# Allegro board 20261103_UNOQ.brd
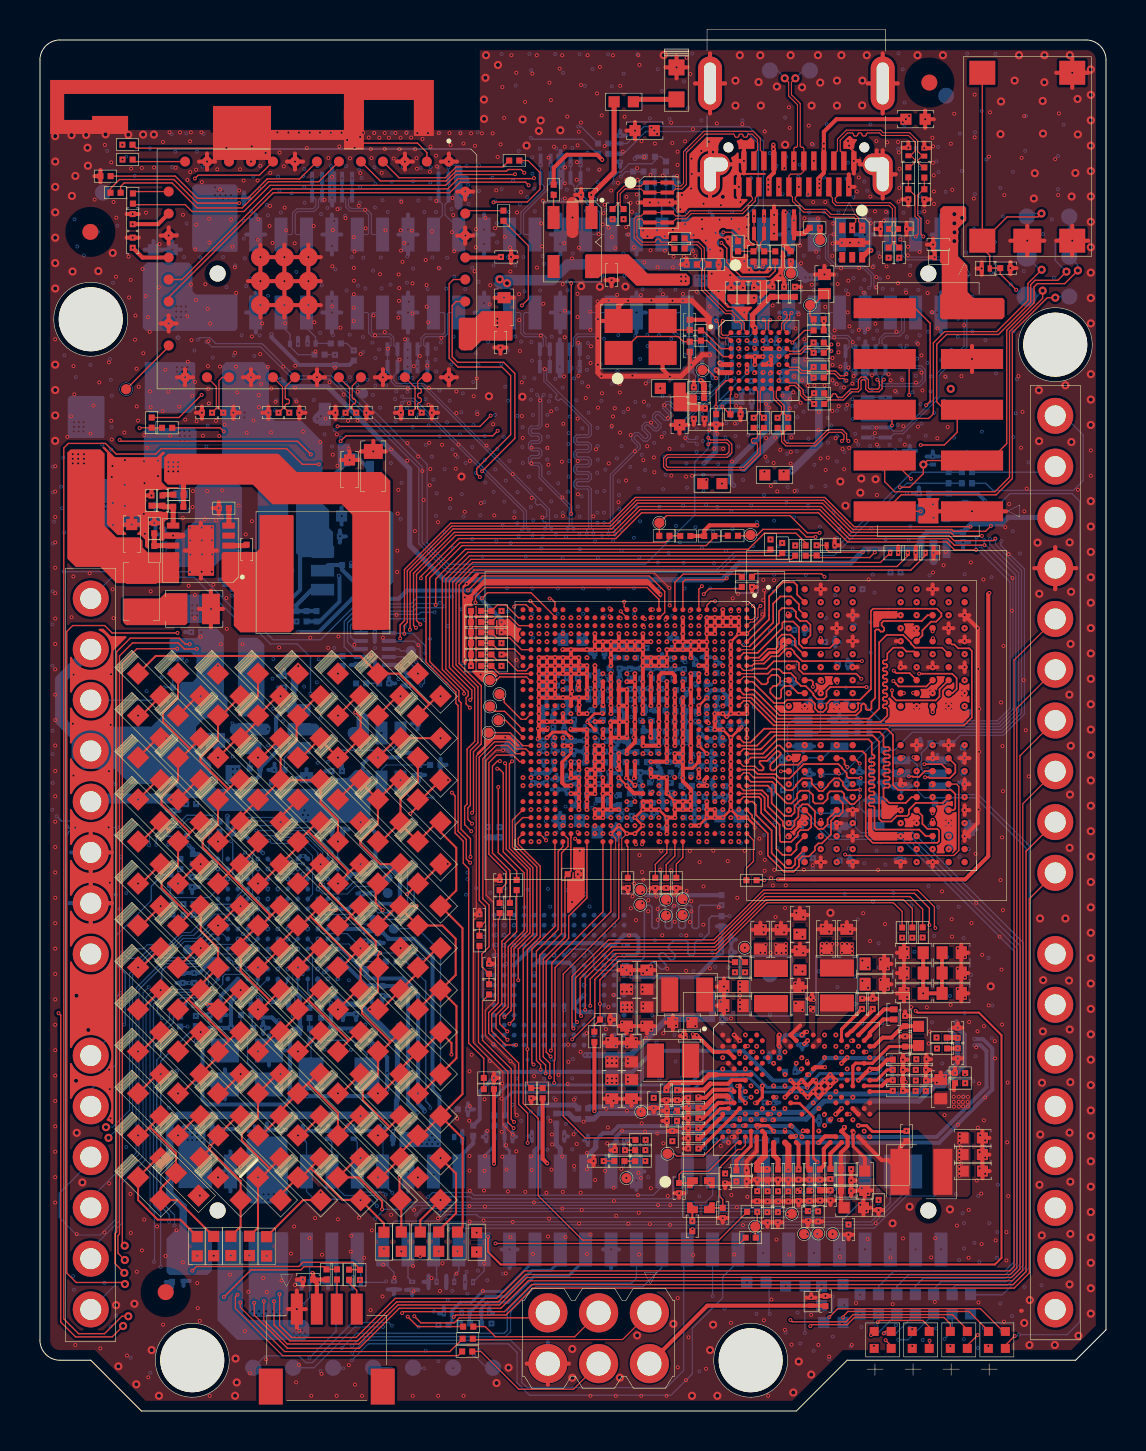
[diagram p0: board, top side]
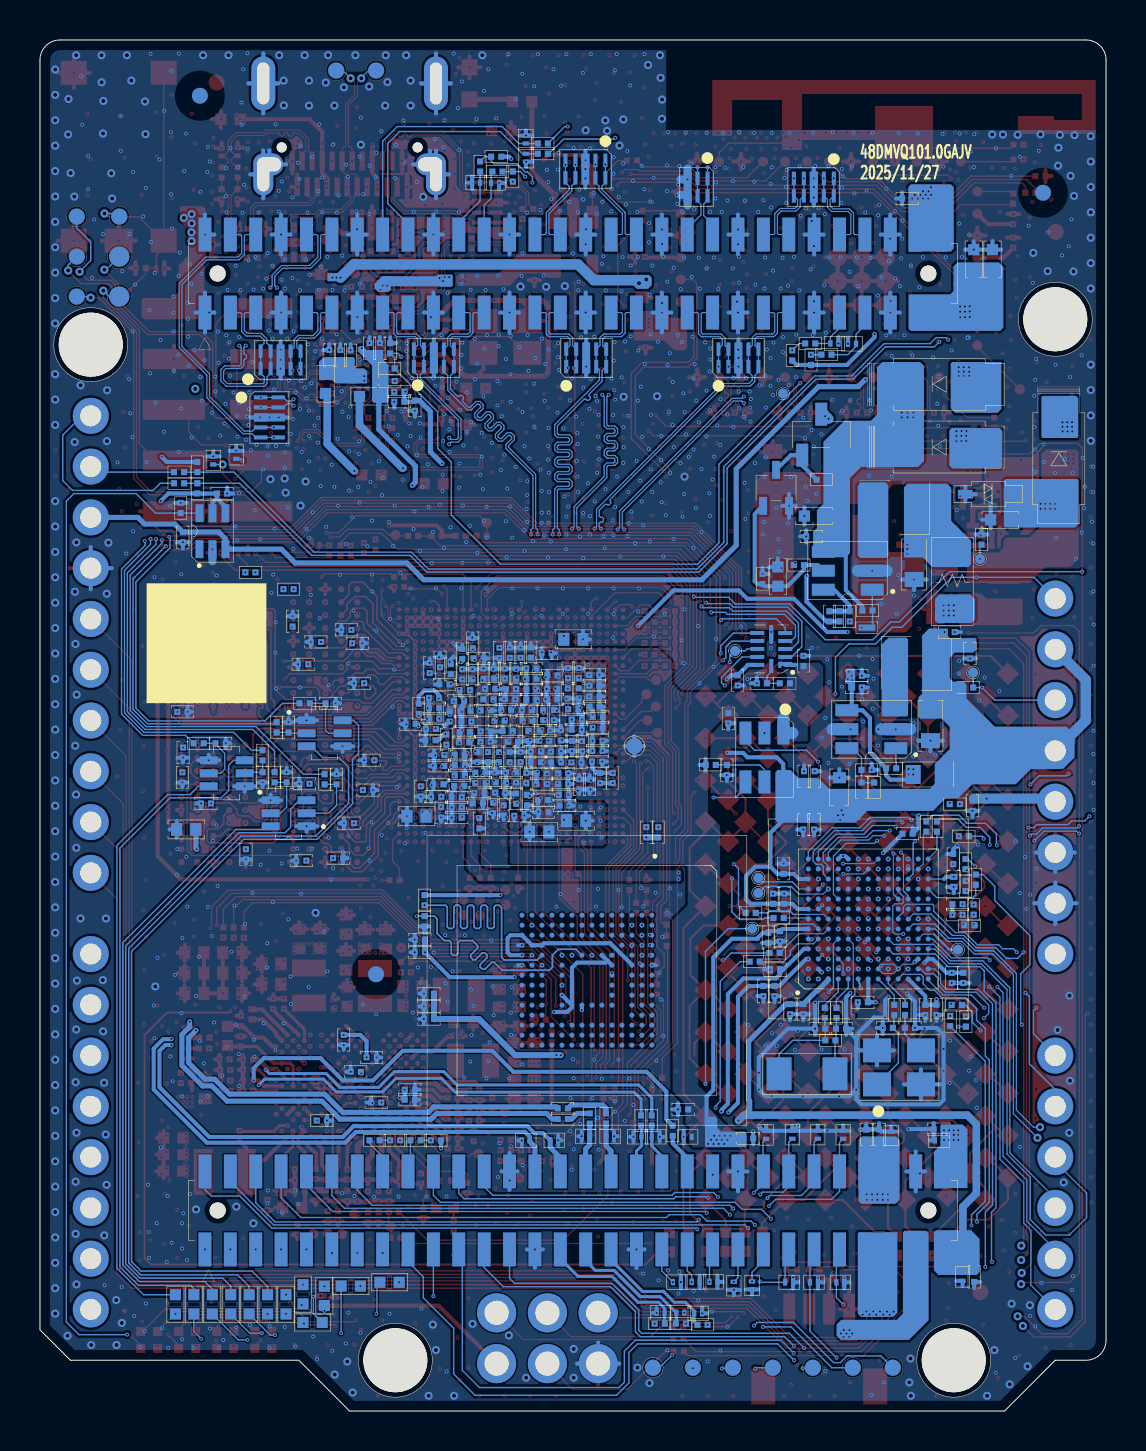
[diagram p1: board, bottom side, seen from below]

Outline 53.34 x 68.58 mm; copper layers: TOP, G2, S3, V4, V5, S6, G7, BOTTOM. Coordinates in mm from the lower left corner of the outline.
Outline path: 0,67.58 0,3.54 arc(0.29,2.83) 1,2.54 2.54,2.54 5.08,0 37.85,0 40.39,2.54 51.82,2.54 53.34,4.06 53.34,67.58 arc(53.05,68.29) 52.34,68.58 1,68.58 arc(0.29,68.29) 0,67.58

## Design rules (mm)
constraint set DEFAULT: min track width 0.066
net group DP_MUX_SSRXN1_C: nets MUX_SSRXN1_C MUX_SSRXP1_C
net group DP_MUX_SSRXN2_C: nets MUX_SSRXN2_C MUX_SSRXP2_C
net group EAR_M_R: nets EAR_M_R EAR_P_R
net group EBI0_CKE: nets EBI0_CKE_0 EBI0_CKE_1
net group EBI0_CLK: nets EBI0_CLK_M EBI0_CLK_P
net group EBI0_DQS_0: nets EBI0_DQS_0_M EBI0_DQS_0_P
net group EBI0_DQS_1: nets EBI0_DQS_1_M EBI0_DQS_1_P
net group EBI1_CKE: nets EBI1_CKE_0 EBI1_CKE_1
net group EBI1_CLK: nets EBI1_CLK_M EBI1_CLK_P
net group EBI1_DQS_0: nets EBI1_DQS_0_M EBI1_DQS_0_P
net group EBI1_DQS_1: nets EBI1_DQS_1_M EBI1_DQS_1_P
net group LINEOUT: nets LINEOUT_M LINEOUT_P
net group LINEOUT_CONN: nets LINEOUT_M_CONN LINEOUT_P_CONN
net group LINEOUT_P_C: nets LINEOUT_M_C LINEOUT_P_C
net group MG_CMD: nets WL_CMD_CLK WL_CMD_DATA
net group MIPI_DSI0_CLK_M: nets MIPI_DSI0_CLK_M MIPI_DSI0_CLK_M_CONN
net group MIPI_DSI0_CLK_P: nets MIPI_DSI0_CLK_P MIPI_DSI0_CLK_P_CONN
net group MIPI_DSI0_L0_M: nets MIPI_DSI0_L0_M MIPI_DSI0_L0_M_CONN
net group MIPI_DSI0_L0_P: nets MIPI_DSI0_L0_P MIPI_DSI0_L0_P_CONN
net group MIPI_DSI0_L1_M: nets MIPI_DSI0_L1_M MIPI_DSI0_L1_M_CONN
net group MIPI_DSI0_L1_P: nets MIPI_DSI0_L1_P MIPI_DSI0_L1_P_CONN
net group MIPI_DSI0_L3_M: nets MIPI_DSI0_L3_M MIPI_DSI0_L3_M_CONN
net group MIPI_DSI0_L3_P: nets MIPI_DSI0_L3_P MIPI_DSI0_L3_P_CONN
net group MUX_SBU1: nets MUX_SBU1 SBU1_AUXP
net group MUX_SBU2: nets MUX_SBU2 SBU2_AUXN
net group MUX_SSRXN2: nets MUX_SSRXN2 MUX_SSRXP2
net group MUX_SSRXP1: nets MUX_SSRXN1 MUX_SSRXP1
net group MUX_SSTXN1_C: nets MUX_SSTXN1 MUX_SSTXP1
net group MUX_SSTXN2: nets MUX_SSTXN2 MUX_SSTXP2
net group MUX_SSTXN2_C: nets MUX_SSTXN2_C MUX_SSTXP2_C
net group MUX_SSTXP1_C: nets MUX_SSTXN1_C MUX_SSTXP1_C
net group SDC1_CLK: nets SDC1_CLK SDC1_CLK_TR
net group VFB_S3: nets VFB_NEG_S3 VFB_S3
net group VFB_S4: nets VFB_NEG_S4 VFB_S4
net group VSNS_S1A_APC: nets VSNS_S1A_APC_M VSNS_S1A_APC_P
net group VSNS_S2A_CX: nets VSNS_S2A_CX_M VSNS_S2A_CX_P
net group CLS_CRITICAL: nets SOC_I2S_D0_R SOC_I2S_SCK SOC_I2S_SCK_R SOC_I2S_WS SOC_I2S_WS_R SOC_UART_RX_SE4 SOC_UART_TX_SE4
net group CLS_LED_MATRIX: nets LED_MATRIX_0 LED_MATRIX_0_R LED_MATRIX_1 LED_MATRIX_1_R LED_MATRIX_2 LED_MATRIX_2_R LED_MATRIX_3 LED_MATRIX_3_R LED_MATRIX_4 LED_MATRIX_4_R LED_MATRIX_5 LED_MATRIX_5_R LED_MATRIX_6 LED_MATRIX_6_R LED_MATRIX_7 LED_MATRIX_7_R LED_MATRIX_8 LED_MATRIX_8_R LED_MATRIX_9 LED_MATRIX_9_R LED_MATRIX_10 LED_MATRIX_10_R LED_MATRIX_11
net group CLS_POWER: nets AVDD1P0V AVDD1P8V AVDD3P0V DVDD1P0V DVDD1P8V VBUS_DIV8 VCOIN VCONN_IN VREF_LPDDR3 VREF_MSM_1P25V VREF_TXDAC_1P25V VREG_L3A_0P6V VREG_L4A_2P96V VREG_L5A_1P232V VREG_L6A_0P9V VREG_L7A_0P664V VREG_L8A_1P0V VREG_L9A_1P0V VREG_L10A_1P3V VREG_L11A_1P0V VREG_L12A_0P9V VREG_L13A_1P8V VREG_L14A_1P8V VREG_L16A_1P8V VREG_L17A_3P0V VREG_L18A_1P8V VREG_L19A_1P8V VREG_L21A_2P96V VREG_L22A_3P3V VREG_S1A_0P8V VREG_XO VSW_S1 VSW_S2 VSW_S3 VSW_S4
net group CLS_SINGEL-50R: nets ANT_CH0 FM_ANT LNBBCLK1 LNBBCLK2 LNBBCLK2_R MUX_XTAL_IN MUX_XTAL_OUT RFCLK2 RTC_SLEEP_CLK RTC_SLEEP_CLK_R SLEEP_CLK SM_LNBBCLK1 SWR_RX_CLK SWR_RX_CLK_R SWR_RX_DATA0 SWR_RX_DATA0_R SWR_RX_DATA1 SWR_RX_DATA1_R SWR_TX_CLK SWR_TX_CLK_R SWR_TX_DATA0 SWR_TX_DATA0_R WCN_RFCLK2 WCN_RFCLK2_R WLAN_XO_CLK
net group EBI0_CA_CS: nets EBI0_CA_0 EBI0_CA_1 EBI0_CA_2 EBI0_CA_3 EBI0_CA_4 EBI0_CA_5 EBI0_CS_0 EBI0_CS_1
net group EBI0_DQ0-7: nets EBI0_DMI_0 EBI0_DQ0 EBI0_DQ1 EBI0_DQ2 EBI0_DQ3 EBI0_DQ4 EBI0_DQ5 EBI0_DQ6 EBI0_DQ7
net group EBI0_DQ8_15: nets EBI0_DMI_1 EBI0_DQ8 EBI0_DQ9 EBI0_DQ10 EBI0_DQ11 EBI0_DQ12 EBI0_DQ13 EBI0_DQ14 EBI0_DQ15
net group EBI1_CA_CS: nets EBI1_CA_0 EBI1_CA_1 EBI1_CA_2 EBI1_CA_3 EBI1_CA_4 EBI1_CA_5 EBI1_CS_0 EBI1_CS_1
net group EBI1_DQ0_7: nets EBI1_DMI_0 EBI1_DQ0 EBI1_DQ1 EBI1_DQ2 EBI1_DQ3 EBI1_DQ4 EBI1_DQ5 EBI1_DQ6 EBI1_DQ7
net group EBI1_DQ8_15: nets EBI1_DMI_1 EBI1_DQ8 EBI1_DQ9 EBI1_DQ10 EBI1_DQ11 EBI1_DQ12 EBI1_DQ13 EBI1_DQ14 EBI1_DQ15
net group MIPI_DSI0_L2_M: nets MIPI_DSI0_L2_M
net group MIPI_DSI0_L2_P: nets MIPI_DSI0_L2_P
net group SDC1: nets SDC1_CMD SDC1_DATA_0 SDC1_DATA_1 SDC1_DATA_2 SDC1_DATA_3 SDC1_DATA_4 SDC1_DATA_5 SDC1_DATA_6 SDC1_DATA_7 SDC1_RCLK

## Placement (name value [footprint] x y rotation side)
ANT1  CLIP2P  [ANT2_1920X400_A]  15.71 64.83 0 top
C501  2.2UF/6.3V  [C0201_H04_T30]  42.72 19.84 0 top
C502  1UF/6.3V  [C0201_H040]  43.29 19.51 180 top
C503  1UF/6.3V  [C0201_H040]  43.29 18.49 180 top
C504  1UF/6.3V  [C0201_H040]  41.13 20.37 180 top
C505  1UF/6.3V  [C0201_H040]  42.93 17.58 90 top
C506  1UF/6.3V  [C0201_H040]  41.66 20.37 180 top
C507  680PF/25V  [C0201_H030]  42.93 17.07 90 top
C508  470PF/50V  [C0201_H030]  42.93 16.54 90 top
C509  680PF/25V  [C0201_H030]  42.93 16.02 90 top
C510  33PF/50V  [C0201_H030]  44.08 17.06 90 top
C511  33PF/50V  [C0201_H030]  44.08 16.53 90 top
C512  100NF/6.3V  [C0201_H030]  44.1 17.59 90 top
C513  100NF/6.3V  [C0201_H030]  27.18 14.61 270 bottom
C514  100NF/6.3V  [C0201_H030]  27.18 15.14 270 bottom
C601  4.7UF/10V  [C0402_H060]  40.72 10.17 90 top
C602  1UF/10V  [C0201_H030]  40.34 11.53 90 top
C603  100NF/10V  [C0201_H030]  40.34 11.01 90 top
C604  10UF/10V  [C0402_H060]  46.68 12 90 top
C605  10UF/10V  [C0402_H060]  46.67 12.83 90 top
C606  10UF/10V  [C0402_H060]  46.67 13.66 90 top
C607  10UF/6.3V  [C0402_H07_T30]  45.07 16.1 180 top
C608  4.7UF/10V  [C0402_H060]  41.27 11.52 0 top
C609  27NF/16V  [C0201_H030]  43.36 13.76 0 top
C610  4.7UF/6.3V  [C0201_H060]  40.46 9.07 0 top
C701  7PF/25V  [C0201_H030]  31.98 11.15 0 top
C702  7PF/25V  [C0201_H030]  34.16 9.91 0 top
C703  1000PF/50V  [C0201_H030]  32.64 9.25 180 top
C704  1UF/6.3V  [C0201_H040]  34.28 11.63 0 top
C705  1UF/6.3V  [C0201_H040]  35.1 11.48 90 top
C706  4.7UF/6.3V  [C0201_H060]  35.1 12.04 90 top
C707  10PF/50V  [C0201_H030]  29.02 13.05 270 top
C708  10UF/6.3V  [C0402_H07_T30]  43.71 22.92 270 top
C709  10UF/6.3V  [C0402_H07_T30]  45.62 22.92 90 top
C710  10UF/6.3V  [C0402_H07_T30]  45.62 21.91 90 top
C711  10UF/6.3V  [C0402_H07_T30]  43.71 21.91 270 top
C712  10UF/6.3V  [C0402_H07_T30]  45.62 20.89 90 top
C713  10UF/6.3V  [C0402_H07_T30]  43.71 20.89 270 top
C714  1UF/6.3V  [C0201_H040]  31.62 15.02 270 top
C715  1UF/6.3V  [C0201_H040]  31.62 14.51 270 top
C716  100NF/10V  [C0201_H030]  31.64 13.75 180 top
C717  100NF/10V  [C0201_H030]  36.4 9.69 0 top
C718  100NF/6.3V  [C0201_H030]  38.5 10.77 0 top
C719  100NF/6.3V  [C0201_H030]  30.71 15.41 0 top
C720  0  [C0201_H030]  28.99 12.5 270 top
C721  22PF/50V  [C0201_H030]  27.95 12.5 270 top
C801  1UF/6.3V  [C0201_H040]  38.14 18.56 180 bottom
C802  1UF/6.3V  [C0201_H040]  36.75 17.69 90 bottom
C803  1UF/6.3V  [C0201_H040]  34.84 15.57 90 bottom
C804  1UF/6.3V  [C0201_H040]  34.84 16.07 90 bottom
C805  1UF/6.3V  [C0201_H040]  35.89 10.74 0 top
C806  10UF/6.3V  [C0402_H07_T30]  34.7 20.28 270 top
C807  10UF/6.3V  [C0402_H07_T30]  34.7 21.23 270 top
C808  10UF/6.3V  [C0402_H07_T30]  41.76 21.35 90 top
C809  10UF/6.3V  [C0402_H07_T30]  41.76 22.36 90 top
C810  10UF/6.3V  [C0402_H07_T30]  38.02 24.33 180 top
C811  10UF/6.3V  [C0402_H07_T30]  38.03 22.54 180 top
C812  1UF/6.3V  [C0201_H040]  37.96 11.83 0 top
C813  1UF/6.3V  [C0201_H040]  32.69 14.15 270 top
C814  1UF/6.3V  [C0201_H040]  32.69 13.64 270 top
C815  2.2UF/6.3V  [C0201_H030]  32.69 14.66 270 top
C816  2.2UF/6.3V  [C0201_H030]  31.88 15.8 0 top
C817  1UF/6.3V  [C0201_H040]  32.69 15.67 270 top
C818  4.7UF/6.3V  [C0201_H060]  31.34 15.8 0 top
C819  2.2UF/6.3V  [C0201_H030]  32.69 15.16 270 top
C820  2.2UF/6.3V  [C0201_H030]  32.69 13.13 270 top
C821  2.2UF/6.3V  [C0201_H030]  37.45 10.74 0 top
C822  4.7UF/6.3V  [C0201_H060]  37.45 11.83 0 top
C823  4.7UF/6.3V  [C0201_H060]  36.4 11.83 0 top
C824  1UF/6.3V  [C0201_H040]  35.89 11.83 0 top
C825  2.2UF/6.3V  [C0201_H030]  36.93 11.83 0 top
C826  4.7UF/6.3V  [C0201_H060]  38.51 11.83 0 top
C827  1UF/6.3V  [C0201_H040]  39.55 11.85 0 top
C828  1UF/6.3V  [C0201_H040]  39.02 11.83 0 top
C829  4.7UF/6.3V  [C0201_H060]  37.96 10.76 0 top
C830  4.7UF/6.3V  [C0201_H060]  36.93 10.74 0 top
C831  4.7UF/6.3V  [C0201_H060]  39.03 10.79 0 top
C832  1UF/6.3V  [C0201_H040]  39.55 10.79 0 top
C901  1UF/10V  [C0201_H030]  36.52 15.43 270 bottom
C902  1UF/10V  [C0201_H030]  37.54 16.97 270 bottom
C1001  1UF/10V  [C0201_H030]  38.63 20.37 180 top
C1002  10UF/10V  [C0402_H060]  37.97 20.73 180 top
C1003  10UF/10V  [C0402_H060]  32.15 19.43 270 top
C1004  1UF/10V  [C0201_H030]  32.5 18.76 270 top
C1005  10UF/6.3V  [C0402_H07_T30]  29.35 19.73 0 top
C1006  10UF/6.3V  [C0402_H07_T30]  29.35 21.57 180 top
C1007  10UF/6.3V  [C0402_H07_T30]  30.37 21.57 180 top
C1008  10UF/6.3V  [C0402_H07_T30]  30.37 19.73 0 top
C1009  10UF/6.3V  [C0402_H07_T30]  29.6 17.94 180 top
C1010  10UF/6.3V  [C0402_H07_T30]  28.61 16.1 0 top
C1011  10UF/6.3V  [C0402_H07_T30]  28.61 17.94 180 top
C1012  10UF/6.3V  [C0402_H07_T30]  29.6 16.1 0 top
C1101  100NF/6.3V  [C0201_H030]  15.14 37.52 0 bottom
C1102  100NF/6.3V  [C0201_H030]  18.43 36.55 180 bottom
C1103  100NF/6.3V  [C0201_H030]  18.9 34.65 180 bottom
C1104  100NF/6.3V  [C0201_H030]  14.58 31.75 0 bottom
C1105  4.7UF/6.3V  [C0201_H060]  17.22 36.4 270 bottom
C1106  4.7UF/6.3V  [C0201_H060]  18.97 32.06 180 bottom
C1201  100NF/6.3V  [C0201_H030]  23 26.31 180 top
C1202  33PF/50V  [C0201_H030]  21.99 24.59 180 top
C1203  33PF/50V  [C0201_H030]  22.47 22.12 180 top
C1601  2.7PF/50V  [C0201_H030]  19.35 49.94 90 top
C1602  2.7PF/50V  [C0201_H030]  18.31 49.94 270 top
C1603  2.7PF/50V  [C0201_H030]  9.42 49.94 90 top
C1604  2.7PF/50V  [C0201_H030]  8.36 49.94 270 top
C1701  1UF/6.3V  [C0201_H040]  30.38 32.71 180 bottom
C1702  100NF/6.3V  [C0201_H030]  24.68 31.66 180 bottom
C1703  100NF/6.3V  [C0201_H030]  25.32 31.66 180 bottom
C1704  100NF/6.3V  [C0201_H030]  26.66 35.11 90 bottom
C1705  10UF/6.3V  [C0402_H07_T30]  26.51 29.53 90 bottom
C1706  10UF/6.3V  [C0402_H07_T30]  39.34 23.62 180 top
C1707  10UF/6.3V  [C0402_H07_T30]  28.36 28.97 270 bottom
C1708  10UF/6.3V  [C0402_H07_T30]  40.37 23.62 180 top
C1709  100NF/6.3V  [C0201_H030]  27.51 32.44 90 bottom
C1710  100NF/6.3V  [C0201_H030]  28.53 32.45 270 bottom
C1711  2.2UF/6.3V  [C0201_H030]  29.77 31.95 270 bottom
C1712  2.2UF/6.3V  [C0201_H030]  29.85 32.71 0 bottom
C1713  100NF/6.3V  [C0201_H030]  28.24 31.9 270 bottom
C1714  470NF/6.3V  [C0201_H030]  27.12 30.82 90 bottom
C1715  470NF/6.3V  [C0201_H030]  28.24 31.36 270 bottom
C1716  470NF/6.3V  [C0201_H030]  29.29 32.71 0 bottom
C1717  100NF/6.3V  [C0201_H030]  27.51 32.98 90 bottom
C1718  100NF/6.3V  [C0201_H030]  28.97 30.56 180 bottom
C1719  100NF/6.3V  [C0201_H030]  28.53 32.98 270 bottom
C1720  100NF/6.3V  [C0201_H030]  27.16 31.36 90 bottom
C1721  100NF/6.3V  [C0201_H030]  27.09 30.28 90 bottom
C1722  2.2UF/6.3V  [C0201_H030]  28.11 33.53 270 bottom
C1723  2.2UF/6.3V  [C0201_H030]  28.15 29.95 270 bottom
C1724  100NF/6.3V  [C0201_H030]  27.16 31.9 90 bottom
C1725  100NF/6.3V  [C0201_H030]  28.16 30.56 270 bottom
C1727  4.7UF/6.3V  [C0201_H060]  32.33 31.8 90 bottom
C1728  2.2UF/6.3V  [C0201_H030]  28.78 37.94 0 bottom
C1729  100NF/6.3V  [C0201_H030]  31.04 35.04 90 bottom
C1730  100NF/6.3V  [C0201_H030]  31.04 34 90 bottom
C1731  100NF/6.3V  [C0201_H030]  32.34 32.82 90 bottom
C1732  470NF/6.3V  [C0201_H030]  28.75 36.09 270 bottom
C1733  10NF/10V  [C0201_H030]  32.37 35.52 90 bottom
C1734  1UF/6.3V  [C0201_H040]  28.75 35.58 270 bottom
C1735  1UF/6.3V  [C0201_H040]  28.94 34.54 270 bottom
C1736  2.2UF/6.3V  [C0201_H030]  31.04 33.49 90 bottom
C1737  2.2UF/6.3V  [C0201_H030]  31.14 36.89 0 bottom
C1738  470NF/6.3V  [C0201_H030]  32.85 34.74 180 bottom
C1739  100NF/6.3V  [C0201_H030]  30.81 36.12 90 bottom
C1740  100NF/6.3V  [C0201_H030]  28.75 37.14 270 bottom
C1741  100NF/6.3V  [C0201_H030]  28.75 36.63 270 bottom
C1742  1UF/6.3V  [C0201_H040]  31.44 32.72 180 bottom
C1743  1UF/6.3V  [C0201_H040]  26.5 32.44 90 bottom
C1801  10UF/6.3V  [C0402_H07_T30]  34.5 29.76 270 bottom
C1802  10UF/6.3V  [C0402_H07_T30]  26.65 38.6 90 bottom
C1803  10UF/6.3V  [C0402_H07_T30]  36.04 23.59 180 top
C1804  10UF/6.3V  [C0402_H07_T30]  37.08 23.59 180 top
C1805  1UF/6.3V  [C0201_H040]  27.7 36.8 270 bottom
C1806  1UF/6.3V  [C0201_H040]  27.7 36.12 270 bottom
C1807  2.2UF/6.3V  [C0201_H030]  27.63 34.81 180 bottom
C1808  100NF/6.3V  [C0201_H030]  29.81 35.6 270 bottom
C1809  100NF/6.3V  [C0201_H030]  29.94 34.01 270 bottom
C1810  100NF/6.3V  [C0201_H030]  32.08 36.06 270 bottom
C1811  100NF/6.3V  [C0201_H030]  32.08 33.96 270 bottom
C1812  100NF/6.3V  [C0201_H030]  30.9 35.6 270 bottom
C1813  100NF/6.3V  [C0201_H030]  27.71 35.6 270 bottom
C1814  1UF/6.3V  [C0201_H040]  30.02 35.08 270 bottom
C1815  1UF/6.3V  [C0201_H040]  32.12 33.46 270 bottom
C1816  1UF/6.3V  [C0201_H040]  30.34 34.53 90 bottom
C1817  1UF/6.3V  [C0201_H040]  31.3 31.93 90 bottom
C1818  4.7UF/6.3V  [C0201_H060]  30.61 36.89 0 bottom
C1819  470NF/6.3V  [C0201_H030]  29.78 36.11 270 bottom
C1820  2.2UF/6.3V  [C0201_H030]  29.52 36.88 0 bottom
C1821  100NF/6.3V  [C0201_H030]  32.05 35.01 270 bottom
C1822  1UF/6.3V  [C0201_H040]  30.08 36.89 0 bottom
C1823  1UF/6.3V  [C0201_H040]  29.68 33.48 90 bottom
C1824  4.7UF/6.3V  [C0201_H060]  28.06 34.04 90 bottom
C1825  100NF/6.3V  [C0201_H030]  28.89 33.77 180 bottom
C1826  2.2UF/6.3V  [C0201_H030]  26.21 33.27 180 bottom
C1827  100NF/6.3V  [C0201_H030]  26.72 33.27 180 bottom
C1828  100NF/6.3V  [C0201_H030]  27.27 33.8 0 bottom
C1829  1UF/6.3V  [C0201_H040]  25.44 33.53 270 bottom
C1830  1UF/6.3V  [C0201_H040]  34.29 31 180 bottom
C1831  1UF/6.3V  [C0201_H040]  33.84 37.17 0 bottom
C1833  1UF/6.3V  [C0201_H040]  27.99 37.91 270 bottom
C1834  1UF/6.3V  [C0201_H040]  26.35 31.34 0 bottom
C1835  1UF/6.3V  [C0201_H040]  30.92 32.71 180 bottom
C1836  100NF/6.3V  [C0201_H030]  33.51 30.73 270 bottom
C1837  1UF/6.3V  [C0201_H040]  30.35 37.92 180 bottom
C1838  1UF/6.3V  [C0201_H040]  29.35 29.77 90 bottom
C1839  1UF/6.3V  [C0201_H040]  33.36 32.27 270 bottom
C1840  1UF/6.3V  [C0201_H040]  25.44 33.02 270 bottom
C1841  1UF/6.3V  [C0201_H040]  25.84 31.34 0 bottom
C1842  1UF/6.3V  [C0201_H040]  33.27 29.95 180 bottom
C1843  100NF/6.3V  [C0201_H030]  25.46 32.49 90 bottom
C1844  100NF/6.3V  [C0201_H030]  29.51 30.63 0 bottom
C1845  4.7UF/6.3V  [C0201_H060]  32.21 37.87 0 bottom
C1846  4.7UF/6.3V  [C0201_H060]  31.7 36.85 0 bottom
C1847  470NF/6.3V  [C0201_H030]  32.21 36.85 0 bottom
C1848  470NF/6.3V  [C0201_H030]  32.78 37.11 0 bottom
C1849  4.7UF/6.3V  [C0201_H060]  28.98 35.06 270 bottom
C1850  470NF/6.3V  [C0201_H030]  33.36 32.81 270 bottom
C1851  1UF/6.3V  [C0201_H040]  25.44 34.18 90 bottom
C1901  1UF/6.3V  [C0201_H040]  29.01 31.66 0 bottom
C1902  1UF/6.3V  [C0201_H040]  33.1 36.35 270 bottom
C1903  1UF/6.3V  [C0201_H040]  32.33 32.31 90 bottom
C1904  1UF/6.3V  [C0201_H040]  30.14 30.05 180 bottom
C1905  1UF/6.3V  [C0201_H040]  29.83 37.93 0 bottom
C1906  100NF/6.3V  [C0201_H030]  29.29 37.93 0 bottom
C1907  100NF/6.3V  [C0201_H030]  30.31 30.93 90 bottom
C1908  1UF/6.3V  [C0201_H040]  30.53 31.7 0 bottom
C1909  1UF/6.3V  [C0201_H040]  30.66 30.17 180 bottom
C1910  1UF/6.3V  [C0201_H040]  29.77 31.44 270 bottom
C1911  100NF/6.3V  [C0201_H030]  26.48 34.59 90 bottom
C1912  470NF/6.3V  [C0201_H030]  28.16 34.82 180 bottom
C1913  1UF/6.3V  [C0201_H040]  31.39 37.65 90 bottom
C1914  1UF/6.3V  [C0201_H040]  32.01 34.48 270 bottom
C1915  1UF/6.3V  [C0201_H040]  33.61 34.63 270 bottom
C1916  1UF/6.3V  [C0201_H040]  33.62 35.16 270 bottom
C1917  1UF/6.3V  [C0201_H040]  26.49 34.08 90 bottom
C1918  100NF/6.3V  [C0201_H030]  25.43 34.72 90 bottom
C1919  100NF/6.3V  [C0201_H030]  25.61 35.74 90 bottom
C1920  100NF/6.3V  [C0201_H030]  25.61 36.28 90 bottom
C1921  1UF/6.3V  [C0201_H040]  25.61 36.82 90 bottom
C1922  100NF/6.3V  [C0201_H030]  26.92 36.91 0 bottom
C1923  100NF/6.3V  [C0201_H030]  26.38 36.91 0 bottom
C1924  1UF/6.3V  [C0201_H040]  26.93 35.89 180 bottom
C1925  470NF/6.3V  [C0201_H030]  33.4 31.35 270 bottom
C1926  100NF/6.3V  [C0201_H030]  32.49 30.7 270 bottom
C1927  100NF/6.3V  [C0201_H030]  32.36 31.27 270 bottom
C1928  100NF/6.3V  [C0201_H030]  32.49 30.19 270 bottom
C1929  1UF/6.3V  [C0201_H040]  32.49 29.68 270 bottom
C1930  1UF/6.3V  [C0201_H040]  31.43 30.4 90 bottom
C1931  1UF/6.3V  [C0201_H040]  31.35 29.4 180 bottom
C1932  1UF/6.3V  [C0201_H040]  31.35 30.92 90 bottom
C1933  1UF/6.3V  [C0201_H040]  31.3 31.42 90 bottom
C1934  1UF/6.3V  [C0201_H040]  33.78 34.11 270 bottom
C1935  1UF/6.3V  [C0201_H040]  31.68 38.41 0 bottom
C1936  2.2UF/6.3V  [C0201_H030]  33.62 35.67 270 bottom
C1937  1UF/6.3V  [C0201_H040]  33.32 37.46 0 bottom
C1938  2.2UF/6.3V  [C0201_H030]  33.01 33.58 180 bottom
C1939  100NF/6.3V  [C0201_H030]  25.6 35.23 90 bottom
C1940  100NF/6.3V  [C0201_H030]  26.38 35.89 180 bottom
C2101  1UF/6.3V  [C0201_H040]  22.4 28.95 0 bottom
C2102  100NF/10V  [C0201_H030]  23 28.95 0 bottom
C2103  2.2UF/6.3V  [C0201_H030]  33.88 20.24 270 bottom
C2104  100NF/6.3V  [C0201_H030]  33.88 20.88 270 bottom
C2105  2.2UF/6.3V  [C0201_H030]  33.88 19.61 270 bottom
C2106  2.2UF/6.3V  [C0201_H030]  34.33 23.58 270 bottom
C2107  1UF/6.3V  [C0201_H040]  34.33 22.95 270 bottom
C2201  1UF/6.3V  [C0201_H040]  38.01 39.07 270 bottom
C2202  1UF/6.3V  [C0201_H040]  40.7 39.5 0 bottom
C2203  1UF/6.3V  [C0201_H040]  33.8 33.55 270 bottom
C2204  100NF/6.3V  [C0201_H030]  38.42 27.66 90 bottom
C2205  1UF/6.3V  [C0201_H040]  43.03 27.85 180 bottom
C2206  1UF/6.3V  [C0201_H040]  37.88 29.41 270 bottom
C2207  100NF/6.3V  [C0201_H030]  45.03 30.39 270 bottom
C2208  1UF/6.3V  [C0201_H040]  39.53 38.47 270 bottom
C2209  1UF/6.3V  [C0201_H040]  37.37 36.4 270 bottom
C2210  1UF/6.3V  [C0201_H040]  34.8 34.36 270 bottom
C2211  1UF/6.3V  [C0201_H040]  46.21 34.97 90 bottom
C2212  1UF/6.3V  [C0201_H040]  46.21 31.7 180 bottom
C2213  1UF/6.3V  [C0201_H040]  40.27 27.53 270 bottom
C2214  1UF/6.3V  [C0201_H040]  46.18 32.94 180 bottom
C2215  10UF/6.3V  [C0402_H07_T30]  46.02 29.09 270 bottom
C2216  4.7UF/6.3V  [C0201_H060]  36.86 32.55 270 bottom
C2217  100NF/6.3V  [C0201_H030]  40.11 31.38 270 bottom
C2218  1UF/6.3V  [C0201_H040]  37.47 38.41 90 bottom
C2219  1UF/6.3V  [C0201_H040]  40.17 37.36 270 bottom
C2220  1UF/6.3V  [C0201_H040]  36.93 31.06 90 bottom
C2501  2.2UF/6.3V  [C0201_H04_T30]  16.56 22.07 270 bottom
C2502  10UF/6.3V  [C0402_H07_T30]  13.34 31.2 0 bottom
C2503  100NF/6.3V  [C0201_H030]  16.59 21.01 180 bottom
C2504  100NF/6.3V  [C0201_H030]  16.1 25.63 0 bottom
C2505  100NF/6.3V  [C0201_H030]  17.14 21.01 180 bottom
C2506  100NF/6.3V  [C0201_H030]  12.17 20.45 270 bottom
C2507  100NF/6.3V  [C0201_H030]  7.43 24.82 90 bottom
C2508  100NF/6.3V  [C0201_H030]  7.43 25.36 90 bottom
C2509  100NF/6.3V  [C0201_H030]  16.13 27.13 0 bottom
C2510  100NF/6.3V  [C0201_H030]  15.11 31.75 0 bottom
C2511  100NF/6.3V  [C0201_H030]  14.61 29.34 180 bottom
C2512  100NF/6.3V  [C0201_H030]  7.65 27.61 0 bottom
C2513  100NF/6.3V  [C0201_H030]  16.66 25.63 0 bottom
C2514  4.7UF/6.3V  [C0201_H060]  9.93 28.88 90 bottom
C2515  100NF/6.3V  [C0201_H030]  16.9 23.67 180 bottom
C2516  100NF/6.3V  [C0201_H030]  16.31 23.75 180 bottom
C2517  1UF/6.3V  [C0201_H040]  7.72 21.67 180 bottom
C2518  100NF/6.3V  [C0201_H030]  7.14 21.67 180 bottom
C2519  100NF/6.3V  [C0201_H030]  15.15 29.34 180 bottom
C2520  1UF/6.3V  [C0201_H040]  9.04 20.07 180 bottom
C2521  100NF/6.3V  [C0201_H030]  8.48 20.07 180 bottom
C2522  12PF/50V  [C0201_H030]  10.92 19.16 270 bottom
C2523  12PF/50V  [C0201_H030]  9.81 19.16 90 bottom
C2524  4.7UF/6.3V  [C0201_H060]  15.82 20.1 180 bottom
C2525  2.2UF/6.3V  [C0201_H04_T30]  7.62 26.47 180 bottom
C2526  100NF/6.3V  [C0201_H030]  15.15 20.1 180 bottom
C2527  7PF/25V  [C0201_H030]  13.26 19.13 90 bottom
C2528  7PF/25V  [C0201_H030]  14.3 19.13 270 bottom
C2529  100NF/6.3V  [C0201_H030]  44.23 45.89 90 bottom
C2601  220NF/10V  [C0201_H030]  42.99 57.94 0 top
C2602  220NF/10V  [C0201_H030]  42.46 57.94 0 top
C2603  220NF/10V  [C0201_H030]  28.65 59.87 0 top
C2604  220NF/10V  [C0201_H030]  29.2 59.87 0 top
C2605  100NF/6.3V  [C0201_H030]  48.3 57.17 90 top
C2607  10UF/10V  [C0402_H060]  43.81 64.62 90 top
C2608  10UF/10V  [C0402_H060]  30.26 64.05 270 top
C2609  100NF/6.3V  [C0201_H030]  44.94 58.35 270 top
C2610  100NF/6.3V  [C0201_H030]  13.41 6.58 270 top
C2611  100NF/10V  [C0201_H030]  39.3 5.5 180 top
C2614  100NF/6.3V  [C0201_H030]  46.19 43.71 180 bottom
C2615  100NF/6.3V  [C0201_H030]  7.82 38.96 90 bottom
C2616  100NF/6.3V  [C0201_H030]  6.81 37.9 180 bottom
C2617  100NF/10V  [C0201_H030]  6.68 30.28 180 bottom
C2618  0.1UF/50V  [C0402_H060]  5.68 57.61 0 bottom
C2619  0.1UF/50V  [C0402_H060]  6.62 57.61 0 bottom
C2620  100NF/6.3V  [C0201_H030]  9.95 60.65 270 bottom
C2621  100NF/10V  [C0201_H030]  11.35 13.83 0 bottom
C2622  100NF/10V  [C0201_H030]  12 13.82 0 bottom
C2623  100NF/6.3V  [C0201_H030]  21.16 15.09 270 bottom
C2624  100NF/6.3V  [C0201_H030]  17.91 13.64 90 bottom
C2625  100NF/6.3V  [C0201_H030]  6.6 6.71 180 bottom
C2626  100NF/6.3V  [C0201_H030]  8.37 14.1 270 bottom
C2627  330NF/10V  [C0201_H030]  32 58.66 270 top
C2628  330NF/10V  [C0201_H030]  32 58.15 270 top
C2629  330NF/10V  [C0201_H030]  44.25 61.95 0 top
C2630  330NF/10V  [C0201_H030]  43.45 61.96 0 top
C2631  0.1UF/50V  [C0402_H060]  5.29 44.58 270 bottom
C2632  220PF/25V  [C0201_H030]  45.92 17.89 0 top
C2633  220PF/25V  [C0201_H030]  45.92 18.92 180 top
C2701  100NF/10V  [C0201_H030]  42.2 31.7 180 bottom
C2702  100NF/10V  [C0201_H030]  44.3 33.4 90 bottom
C2703  100NF/10V  [C0201_H030]  40.9 34.2 0 bottom
C2704  100NF/10V  [C0201_H030]  38.8 35.4 90 bottom
C2705  100NF/10V  [C0201_H030]  38.5 31.6 0 bottom
C2706  100NF/10V  [C0201_H030]  41 31.7 0 bottom
C2801  4.7UF/10V  [C0402_H060]  14.61 44.77 270 bottom
C2802  100NF/10V  [C0201_H030]  14.75 43.75 270 bottom
C2803  120PF/25V  [C0201_H030]  13.84 39.75 0 bottom
C2804  22UF/6.3V  [C0603_H100]  9.6 42.34 180 bottom
C2805  4.7UF/6.3V  [C0201_H060]  12.47 36.78 90 bottom
C2806  100NF/6.3V  [C0201_H030]  12.47 36.2 90 bottom
C2807  120PF/25V  [C0201_H030]  12.23 31.19 0 bottom
C2808  4.7UF/10V  [C0402_H060]  16.42 41.74 0 bottom
C2809  22UF/6.3V  [C0603_H100]  8.78 34.28 180 bottom
C2810  22UF/25V  [C0805_H150]  5.07 40.99 0 top
C2811  22UF/25V  [C0805_H150]  7.72 40.12 90 top
C2812  0.1UF/50V  [C0402_H060]  4.59 43.86 180 top
C2813  100NF/16V  [C0201_H030]  10.34 43.08 180 top
C2814  22PF/50V  [C0201_H030]  6.13 45.54 0 top
C2815  22UF/10V  [C0603_H090]  16.68 47.25 180 top
C2816  10UF/10V  [C0402_H060]  15.49 47.09 180 top
C2901  4.7UF/6.3V  [C0201_H060]  4.64 59.62 180 top
C2907  4.7UF/6.3V  [C0201_H060]  23.32 57.73 90 top
C2909  4.7UF/6.3V  [C0201_H060]  4.64 58.44 180 top
C2911  10UF/6.3V  [C0402_H07_T30]  23.22 55.21 180 top
C2912  4.7UF/6.3V  [C0201_H060]  23.04 53.45 0 top
C2921  2.7PF/50V  [C0201_H030]  15.04 49.94 270 top
C2922  2.7PF/50V  [C0201_H030]  16.08 49.94 90 top
C2923  2.7PF/50V  [C0201_H030]  12.73 49.94 90 top
C2924  2.7PF/50V  [C0201_H030]  11.68 49.94 270 top
C3001  1UF/6.3V  [C0201_H040]  34.59 55.94 180 top
C3002  100NF/6.3V  [C0201_H030]  35.17 55.93 180 top
C3003  1000PF/50V  [C0201_H030]  35.73 55.94 180 top
C3004  1UF/6.3V  [C0201_H040]  38.31 52.82 0 bottom
C3005  100NF/6.3V  [C0201_H030]  38.87 52.82 0 bottom
C3006  1000PF/50V  [C0201_H030]  37.8 52.81 0 bottom
C3007  1UF/6.3V  [C0201_H040]  34.58 50.29 180 bottom
C3008  100NF/6.3V  [C0201_H030]  35.36 50.48 270 bottom
C3009  1000PF/50V  [C0201_H030]  35.36 50.99 270 bottom
C3010  1UF/6.3V  [C0201_H040]  37.77 55.98 180 top
C3011  100NF/6.3V  [C0201_H030]  37.23 55.98 180 top
C3012  1000PF/50V  [C0201_H030]  36.65 55.99 180 top
C3013  1UF/6.3V  [C0201_H040]  36.34 53.16 0 bottom
C3014  100NF/6.3V  [C0201_H030]  35.84 51.52 90 bottom
C3015  1000PF/50V  [C0201_H030]  36.85 53.16 0 bottom
C3016  10UF/10V  [C0402_H060]  32 49.81 0 top
C3017  100NF/10V  [C0201_H030]  33.25 49.89 0 top
C3018  1000PF/50V  [C0201_H030]  32.72 49.89 0 top
C3019  100NF/10V  [C0201_H030]  35.7 57.76 180 top
C3020  100NF/10V  [C0201_H030]  36.24 57.76 180 top
C3021  36PF/50V  [C0201_H030]  32.51 53.24 0 top
C3022  36PF/50V  [C0201_H030]  32.51 54.33 180 top
C3025  1UF/6.3V  [C0201_H040]  27.33 60.83 270 top
C3026  1UF/6.3V  [C0201_H040]  28.6 56.82 0 top
C3027  10UF/6.3V  [C0402_H07_T30]  39.25 56.37 180 top
C3028  100NF/6.3V  [C0201_H030]  35.82 53.16 0 bottom
D2801  SX34  [SMA_H240]  8.35 51.36 270 bottom
D2802  SX34  [SMA_H240]  2.36 47.63 0 bottom
D2803  SX34  [SMA_H240]  8.35 48.22 270 bottom
D26001  DF2B7ASL  [D_06X03_H030_TOSHIBA]  44.67 47.55 180 bottom
D26002  DF2B7ASL  [D_06X03_H030_TOSHIBA]  43.52 47.83 180 bottom
D26003  DF2B7ASL  [D_06X03_H030_TOSHIBA]  44.97 57.71 90 top
D26005  DF2B7ASL  [D_06X03_H030_TOSHIBA]  44.51 42.93 270 top
D26006  DF2B7ASL  [D_06X03_H030_TOSHIBA]  43.62 42.93 270 top
D26007  DF2B7ASL  [D_06X03_H030_TOSHIBA]  42.74 42.93 270 top
D26008  DF2B7ASL  [D_06X03_H030_TOSHIBA]  39.56 43.3 270 top
D26009  DF2B7ASL  [D_06X03_H030_TOSHIBA]  47.32 57.15 90 top
D26017  DF2B7ASL  [D_06X03_H030_TOSHIBA]  38.59 5.47 0 top
D26046  DF2B7ASL  [D_06X03_H030_TOSHIBA]  29.03 63.6 180 bottom
D26047  DF2B7ASL  [D_06X03_H030_TOSHIBA]  29.02 62.69 0 bottom
D26048  DF2B7ASL  [D_06X03_H030_TOSHIBA]  31.52 61.44 90 bottom
D26049  DF2B7ASL  [D_06X03_H030_TOSHIBA]  30.57 61.43 270 bottom
D26050  DF2B7ASL  [D_06X03_H030_TOSHIBA]  12.71 53.38 90 bottom
D26051  DF2B7ASL  [D_06X03_H030_TOSHIBA]  13.59 53.4 270 bottom
D26063  DF2B7ASL  [D_06X03_H030_TOSHIBA]  29.03 13.53 90 bottom
D26064  DF2B7ASL  [D_06X03_H030_TOSHIBA]  27.61 13.54 270 bottom
D26065  DF2B7ASL  [D_06X03_H030_TOSHIBA]  22.29 4.91 90 bottom
D26066  DF2B7ASL  [D_06X03_H030_TOSHIBA]  21.3 4.91 270 bottom
D26067  DF2B7ASL  [D_06X03_H030_TOSHIBA]  20.41 4.89 270 bottom
D26069  DF2B7ASL  [D_06X03_H030_TOSHIBA]  21.47 6.45 270 bottom
D26070  DF2B7ASL  [D_06X03_H030_TOSHIBA]  20.53 6.46 270 bottom
D26071  DF2B7ASL  [D_06X03_H030_TOSHIBA]  19.64 6.46 270 bottom
D26072  DF2B7ASL  [D_06X03_H030_TOSHIBA]  18.62 6.26 0 bottom
D26073  DF2B7ASL  [D_06X03_H030_TOSHIBA]  17.71 6.28 0 bottom
D26074  DF2B7ASL  [D_06X03_H030_TOSHIBA]  15.86 6.44 270 bottom
D26075  DF2B7ASL  [D_06X03_H030_TOSHIBA]  14.61 6.44 270 bottom
D26076  DF2B7ASL  [D_06X03_H030_TOSHIBA]  13.29 6.44 270 bottom
D26087  DF2B7ASL  [D_06X03_H030_TOSHIBA]  26.04 13.74 90 bottom
D26088  DF2B7ASL  [D_06X03_H030_TOSHIBA]  24.82 13.74 270 bottom
D26089  DF2B7ASL  [D_06X03_H030_TOSHIBA]  23.44 13.72 90 bottom
D26090  DF2B7ASL  [D_06X03_H030_TOSHIBA]  22.53 13.72 270 bottom
D26091  DF2B7ASL  [D_06X03_H030_TOSHIBA]  17.01 13.81 180 bottom
D26092  DF2B7ASL  [D_06X03_H030_TOSHIBA]  15.7 13.82 180 bottom
D26093  DF2B7ASL  [D_06X03_H030_TOSHIBA]  14.42 13.82 180 bottom
D26094  DF2B7ASL  [D_06X03_H030_TOSHIBA]  13.15 13.82 180 bottom
D26097  DF2B7ASL  [D_06X03_H030_TOSHIBA]  10.75 13.78 180 bottom
D26099  DF2B7ASL  [D_06X03_H030_TOSHIBA]  20.93 13.71 90 bottom
D26100  DF2B7ASL  [D_06X03_H030_TOSHIBA]  7.18 6.71 0 bottom
D26101  DF2B7ASL  [D_06X03_H030_TOSHIBA]  8.36 13.54 90 bottom
D26102  TVW060305VB1SCA1  [D_06X03_H04_INPAQ]  44.25 62.97 180 top
D26103  TVW060305VB1SCA1  [D_06X03_H04_INPAQ]  43.45 62.99 180 top
D26104  TVW060305VB1SCA1  [D_06X03_H04_INPAQ]  43.16 59.13 90 top
D26105  TVW060305VB1SCA1  [D_06X03_H04_INPAQ]  42.26 59.13 270 top
D26201  PJGBLC24C  [SOD323FL_H090_UM]  5.89 45.86 90 bottom
D27001  BLU_LED  [LED0603_H050]  19.47 36.32 225 top
D27002  BLU_LED  [LED0603_H050]  19.47 34.22 225 top
D27003  BLU_LED  [LED0603_H050]  19.47 32.12 225 top
D27004  BLU_LED  [LED0603_H050]  19.47 30.02 225 top
D27005  BLU_LED  [LED0603_H050]  19.47 27.92 225 top
D27006  BLU_LED  [LED0603_H050]  19.47 25.82 225 top
D27007  BLU_LED  [LED0603_H050]  19.47 23.72 225 top
D27008  BLU_LED  [LED0603_H050]  19.47 21.62 225 top
D27009  BLU_LED  [LED0603_H050]  19.47 19.52 225 top
D27010  BLU_LED  [LED0603_H050]  19.47 17.42 225 top
D27011  BLU_LED  [LED0603_H050]  19.47 15.32 225 top
D27012  BLU_LED  [LED0603_H050]  19.47 13.22 225 top
D27013  BLU_LED  [LED0603_H050]  19.47 11.12 225 top
D27014  BLU_LED  [LED0603_H050]  17.47 36.32 225 top
D27015  BLU_LED  [LED0603_H050]  17.47 34.22 225 top
D27016  BLU_LED  [LED0603_H050]  17.47 32.12 225 top
D27017  BLU_LED  [LED0603_H050]  17.47 30.02 225 top
D27018  BLU_LED  [LED0603_H050]  17.47 27.92 225 top
D27019  BLU_LED  [LED0603_H050]  17.47 25.82 225 top
D27020  BLU_LED  [LED0603_H050]  17.47 23.72 225 top
D27021  BLU_LED  [LED0603_H050]  17.47 21.62 225 top
D27022  BLU_LED  [LED0603_H050]  17.47 19.52 225 top
D27023  BLU_LED  [LED0603_H050]  17.47 17.42 225 top
D27024  BLU_LED  [LED0603_H050]  17.47 15.32 225 top
D27025  BLU_LED  [LED0603_H050]  17.47 13.22 225 top
D27026  BLU_LED  [LED0603_H050]  17.47 11.12 225 top
D27027  BLU_LED  [LED0603_H050]  15.47 36.32 225 top
D27028  BLU_LED  [LED0603_H050]  15.47 34.22 225 top
D27029  BLU_LED  [LED0603_H050]  15.47 32.12 225 top
D27030  BLU_LED  [LED0603_H050]  15.47 30.02 225 top
D27031  BLU_LED  [LED0603_H050]  15.47 27.92 225 top
D27032  BLU_LED  [LED0603_H050]  15.47 25.82 225 top
D27033  BLU_LED  [LED0603_H050]  15.47 23.72 225 top
D27034  BLU_LED  [LED0603_H050]  15.47 21.62 225 top
D27035  BLU_LED  [LED0603_H050]  15.47 19.52 225 top
D27036  BLU_LED  [LED0603_H050]  15.47 17.42 225 top
D27037  BLU_LED  [LED0603_H050]  15.47 15.32 225 top
D27038  BLU_LED  [LED0603_H050]  15.47 13.22 225 top
D27039  BLU_LED  [LED0603_H050]  15.47 11.12 225 top
D27040  BLU_LED  [LED0603_H050]  13.47 36.32 225 top
D27041  BLU_LED  [LED0603_H050]  13.47 34.22 225 top
D27042  BLU_LED  [LED0603_H050]  13.47 32.12 225 top
D27043  BLU_LED  [LED0603_H050]  13.47 30.02 225 top
D27044  BLU_LED  [LED0603_H050]  13.47 27.92 225 top
D27045  BLU_LED  [LED0603_H050]  13.47 25.82 225 top
D27046  BLU_LED  [LED0603_H050]  13.47 23.72 225 top
D27047  BLU_LED  [LED0603_H050]  13.47 21.62 225 top
D27048  BLU_LED  [LED0603_H050]  13.47 19.52 225 top
D27049  BLU_LED  [LED0603_H050]  13.47 17.42 225 top
D27050  BLU_LED  [LED0603_H050]  13.47 15.32 225 top
D27051  BLU_LED  [LED0603_H050]  13.47 13.22 225 top
D27052  BLU_LED  [LED0603_H050]  13.47 11.12 225 top
D27053  BLU_LED  [LED0603_H050]  11.47 36.32 225 top
D27054  BLU_LED  [LED0603_H050]  11.47 34.22 225 top
D27055  BLU_LED  [LED0603_H050]  11.47 32.12 225 top
D27056  BLU_LED  [LED0603_H050]  11.47 30.02 225 top
D27057  BLU_LED  [LED0603_H050]  11.47 27.92 225 top
D27058  BLU_LED  [LED0603_H050]  11.47 25.82 225 top
D27059  BLU_LED  [LED0603_H050]  11.47 23.72 225 top
D27060  BLU_LED  [LED0603_H050]  11.47 21.62 225 top
D27061  BLU_LED  [LED0603_H050]  11.47 19.52 225 top
D27062  BLU_LED  [LED0603_H050]  11.47 17.42 225 top
D27063  BLU_LED  [LED0603_H050]  11.47 15.32 225 top
D27064  BLU_LED  [LED0603_H050]  11.47 13.22 225 top
D27065  BLU_LED  [LED0603_H050]  11.47 11.12 225 top
D27066  BLU_LED  [LED0603_H050]  9.47 36.32 225 top
D27067  BLU_LED  [LED0603_H050]  9.47 34.22 225 top
D27068  BLU_LED  [LED0603_H050]  9.47 32.12 225 top
D27069  BLU_LED  [LED0603_H050]  9.47 30.02 225 top
D27070  BLU_LED  [LED0603_H050]  9.47 27.92 225 top
D27071  BLU_LED  [LED0603_H050]  9.47 25.82 225 top
D27072  BLU_LED  [LED0603_H050]  9.47 23.72 225 top
D27073  BLU_LED  [LED0603_H050]  9.47 21.62 225 top
D27074  BLU_LED  [LED0603_H050]  9.47 19.52 225 top
D27075  BLU_LED  [LED0603_H050]  9.47 17.42 225 top
D27076  BLU_LED  [LED0603_H050]  9.47 15.32 225 top
D27077  BLU_LED  [LED0603_H050]  9.47 13.22 225 top
D27078  BLU_LED  [LED0603_H050]  9.47 11.12 225 top
D27079  BLU_LED  [LED0603_H050]  7.47 36.32 225 top
D27080  BLU_LED  [LED0603_H050]  7.47 34.22 225 top
D27081  BLU_LED  [LED0603_H050]  7.47 32.12 225 top
D27082  BLU_LED  [LED0603_H050]  7.47 30.02 225 top
D27083  BLU_LED  [LED0603_H050]  7.47 27.92 225 top
D27084  BLU_LED  [LED0603_H050]  7.47 25.82 225 top
D27085  BLU_LED  [LED0603_H050]  7.47 23.72 225 top
D27086  BLU_LED  [LED0603_H050]  7.47 21.62 225 top
D27087  BLU_LED  [LED0603_H050]  7.47 19.52 225 top
D27088  BLU_LED  [LED0603_H050]  7.47 17.42 225 top
D27089  BLU_LED  [LED0603_H050]  7.47 15.32 225 top
D27090  BLU_LED  [LED0603_H050]  7.47 13.22 225 top
D27091  BLU_LED  [LED0603_H050]  7.37 11.34 225 top
D27092  BLU_LED  [LED0603_H050]  5.47 36.32 225 top
D27093  BLU_LED  [LED0603_H050]  5.47 34.22 225 top
D27094  BLU_LED  [LED0603_H050]  5.47 32.12 225 top
D27095  BLU_LED  [LED0603_H050]  5.47 30.02 225 top
D27096  BLU_LED  [LED0603_H050]  5.47 27.92 225 top
D27097  BLU_LED  [LED0603_H050]  5.47 25.82 225 top
D27098  BLU_LED  [LED0603_H050]  5.47 23.72 225 top
D27099  BLU_LED  [LED0603_H050]  5.47 21.62 225 top
D27100  BLU_LED  [LED0603_H050]  5.47 19.52 225 top
D27101  BLU_LED  [LED0603_H050]  5.47 17.42 225 top
D27102  BLU_LED  [LED0603_H050]  5.47 15.32 225 top
D27103  BLU_LED  [LED0603_H050]  5.47 13.22 225 top
D27104  BLU_LED  [LED0603_H050]  5.47 11.12 225 top
D27201  GRN_LED  [LED0603_H090]  31.85 66.41 180 top
D27301  RED_BLU_GRN_LED4P  [LED4_10X10_A1_H04]  44.07 3.56 270 top
D27302  RED_BLU_GRN_LED4P  [LED4_10X10_A1_H04]  42.16 3.56 270 top
D27401  RED_BLU_GRN_LED4P  [LED4_10X10_A1_H04]  45.97 3.56 270 top
D27402  RED_BLU_GRN_LED4P  [LED4_10X10_A1_H04]  47.88 3.56 270 top
DRAM1  MT53E512M32D1ZW-046_WT_B  [BGA200P_145X100_H110]  41.86 34.28 180 top
EMMC1  EMMC16G-MW28-GA01_BGA153P  [BGA153P_130X115_05_H090]  25.97 21.55 90 bottom
F501  BEAD_120  [BEAD0402_H060]  43.96 18.76 0 top
JANALOG1  20TW-995  [HEAD14_387X25_2D54_H87_F]  2.54 40.64 270 top
JBTN1  TS-A57AHNP-2-W-S085  [SW5_85X64_H34_P12]  49.4 62.74 270 top
JCTL1  P302V-2X5-ST2-RT  [HEAD2X5P_127X62_254_H970_M]  44.45 50.08 0 top
JDIGITAL1  20TW-994  [HEAD18_477X25_2D54_H87_F]  50.8 5.08 90 top
JMEDIA1  SM2554V6-2X30-SMT-G5-1-RT  [HEAD2X30_385X50_1D27_H48_F_R_P]  26.67 56.9 270 bottom
JMISC1  SM2554V6-2X30-SMT-G5-1-RT  [HEAD2X30_385X50_1D27_H48_F_R_P]  26.67 10.03 270 bottom
JSPI1  HD2X03C-R3H-HH  [HEAD2X3_76X50_2D54_H87_M_PIP]  30.49 4.91 180 top
JUSB1  USB3-24CSW-R9H-H  [USB2X12_89X81_H35]  37.85 65.06 270 top
L601  1UH/4.2A  [L_25X20_H10_D]  44.1 11.96 90 top
L1001  470NH/4.7A  [CHOKE_200X160_H100_A]  39.88 21.29 180 top
L1002  470NH/4.7A  [CHOKE_200X160_H100_A]  36.58 21.26 180 top
L1003  470NH/4.7A  [CHOKE_200X160_H100_A]  32.38 20.83 270 top
L1004  470NH/4.7A  [CHOKE_200X160_H100_A]  31.67 17.53 270 top
L2801  1UH/4.2A  [L_25X20_H10_D]  10.56 45.18 90 bottom
L2802  1UH/4.2A  [L_25X20_H10_D]  9.5 37.39 90 bottom
L2803  3.3UH/4.3A  [CHOKE_60X59_H45_INPAQ]  14.16 41.93 90 top
MCU1  STM32U585AII6TR_BGA169P  [BGA169_70_0D5_H06]  11.9 24.61 270 bottom
NOREF  -  []  31.73 30.25 0 top
NOREF#2  -  []  46.45 44.87 90 top
NOREF#3  -  []  32.46 57.65 0 top
NOREF#4  -  []  25.13 34.57 90 top
NOREF#5  -  []  37.58 29.56 0 top
NOREF#6  -  []  11.13 64.55 0 top
NOREF#7  -  []  38.84 50.67 0 top
NOREF#8  -  []  32.06 37.15 90 top
NOREF#9  -  []  39.87 37.51 0 top
NOREF#10  -  []  37.97 50.54 90 top
NOREF#11  -  []  28.45 37.29 0 top
NOREF#12  -  []  40.78 5.84 0 top
NOREF#13  -  []  42.26 22.12 90 top
NOREF#14  -  []  28.8 55.33 0 top
NOREF#15  -  []  32.92 10.59 0 top
NOREF#16  -  []  29.32 13.2 0 top
NOREF#17  -  []  26.78 34.44 0 top
NOREF#18  -  []  26.36 34.96 90 top
NOREF#19  -  []  47.53 4.91 0 top
NOREF#20  -  []  28.8 55.33 0 top
NOREF#21  -  []  10 41.54 90 top
NOREF#22  -  []  34.54 15.92 90 top
NOREF#23  -  []  44.38 16.38 90 top
NOREF#24  -  []  29.53 62.05 0 top
NOREF#25  -  []  2.54 5.08 90 top
NOREF#26  -  []  15.01 6.53 90 top
NOREF#27  -  []  36.4 43.64 0 top
NOREF#28  -  []  35.32 56.23 90 top
NOREF#29  -  []  21.97 38.11 90 top
NOREF#30  -  []  42.35 32 0 top
NOREF#31  -  []  24.85 57.53 90 top
NOREF#32  -  []  29.48 36.26 0 top
NOREF#33  -  []  22.25 29.25 90 top
NOREF#34  -  []  38.35 11.07 0 top
NOREF#35  -  []  32 58.81 0 top
NOREF#36  -  []  28.86 29.22 90 top
NOREF#37  -  []  21.67 38.71 0 top
NOREF#38  -  []  40.62 23.12 0 top
NOREF#39  -  []  45.39 5.84 0 top
NOREF#40  -  []  44.4 17.44 90 top
NOREF#41  -  []  25.69 31.04 0 top
NOREF#42  -  []  40.95 61.37 0 top
NOREF#43  -  []  29.72 35.23 0 top
NOREF#44  -  []  26.79 33.93 0 top
NOREF#45  -  []  39.81 31.53 0 top
NOREF#46  -  []  29.05 29.62 90 top
NOREF#47  -  []  28.45 30.1 90 top
NOREF#48  -  []  30.26 61.3 0 top
NOREF#49  -  []  43.6 60.56 90 top
NOREF#50  -  []  4.79 57.84 90 top
NOREF#51  -  []  31.53 38.11 0 top
NOREF#52  -  []  38.88 10.49 90 top
NOREF#53  -  []  14.29 6.31 90 top
NOREF#54  -  []  16.46 23.45 90 top
NOREF#55  -  []  47.2 56.96 90 top
NOREF#56  -  []  15.34 50.09 0 top
NOREF#57  -  []  39.5 55.87 90 top
NOREF#58  -  []  32.36 52.94 90 top
NOREF#59  -  [unnamed#2]  6.29 5.95 0 top
NOREF#60  -  []  40.75 41.41 0 top
NOREF#61  -  []  33.91 34.78 90 top
NOREF#62  -  []  16.17 42.24 90 top
NOREF#63  -  []  15.11 45.02 90 top
NOREF#64  -  []  43.21 23.17 90 top
NOREF#65  -  []  12.77 36.04 0 top
NOREF#66  -  []  43.71 18.96 0 top
NOREF#67  -  []  37.67 36.55 90 top
NOREF#68  -  []  33.5 33.7 0 top
NOREF#69  -  []  11.45 31.48 0 top
NOREF#70  -  []  16.74 20.71 90 top
NOREF#71  -  []  27.94 31.51 0 top
NOREF#72  -  []  46.51 34.82 0 top
NOREF#73  -  []  39.45 5.8 90 top
NOREF#74  -  []  6.9 39.9 90 top
NOREF#75  -  []  26.77 37.21 90 top
NOREF#76  -  []  44.55 47.38 90 top
NOREF#77  -  []  33.17 37.16 0 top
NOREF#78  -  []  27.65 12.65 90 top
NOREF#79  -  []  36.1 5.94 90 top
NOREF#80  -  []  30.64 26.72 0 top
NOREF#81  -  []  44.05 4.84 90 top
NOREF#82  -  []  28.86 31.36 0 top
NOREF#83  -  []  31.78 36.21 0 top
NOREF#84  -  []  32.25 65.61 90 top
NOREF#85  -  []  22.99 39.72 90 top
NOREF#86  -  []  12.96 18.98 90 top
NOREF#87  -  []  8.66 50.09 0 top
NOREF#88  -  []  10.38 13.86 90 top
NOREF#89  -  []  38.22 20.23 0 top
NOREF#90  -  []  34.4 13.84 0 top
NOREF#91  -  []  36.75 13.24 90 top
NOREF#92  -  []  38.81 54.91 0 top
NOREF#93  -  []  17.08 48.05 90 top
NOREF#94  -  []  7.5 27.31 0 top
NOREF#95  -  []  15.74 46.59 0 top
NOREF#96  -  []  42.24 59.28 0 top
NOREF#97  -  []  10.59 14.09 0 top
NOREF#98  -  []  33.98 49.31 90 top
NOREF#99  -  []  43.18 27.55 90 top
NOREF#100  -  []  23.04 60.09 0 top
NOREF#101  -  []  22.69 40.32 0 top
NOREF#102  -  []  33.69 19.45 0 top
NOREF#103  -  []  21.16 6.33 0 top
NOREF#104  -  []  37.23 30.91 0 top
NOREF#105  -  []  4.79 59.02 90 top
NOREF#106  -  []  36.64 58.05 0 top
NOREF#107  -  []  42.84 57.64 90 top
NOREF#108  -  []  30.2 13.26 90 top
NOREF#109  -  []  29.04 33.47 90 top
NOREF#110  -  []  6.08 43.89 0 top
NOREF#111  -  []  35.22 41.52 0 top
NOREF#112  -  []  35.06 50.63 0 top
NOREF#113  -  []  26.51 27.15 0 top
NOREF#114  -  []  36.78 11.53 90 top
NOREF#115  -  []  27.89 18.42 90 top
NOREF#116  -  []  33.38 21.63 0 top
NOREF#117  -  []  25.74 33.68 90 top
NOREF#118  -  []  29.85 18.44 90 top
NOREF#119  -  []  17.3 21.31 0 top
NOREF#120  -  []  29.38 33.33 90 top
NOREF#121  -  []  43.11 3.61 90 top
NOREF#122  -  []  32.06 36.55 0 top
NOREF#123  -  []  28.86 31.96 90 top
NOREF#124  -  []  31.75 50.31 0 top
NOREF#125  -  []  42.2 4.84 90 top
NOREF#126  -  []  35.75 26.25 90 top
NOREF#127  -  []  39.44 43.11 90 top
NOREF#128  -  []  32.06 38.17 90 top
NOREF#129  -  []  28.33 62.59 90 top
NOREF#130  -  []  28.68 35.21 0 top
NOREF#131  -  []  37.38 22.26 90 top
NOREF#132  -  []  14.43 31.45 90 top
NOREF#133  -  []  28.54 32.05 90 top
NOREF#134  -  []  14.3 6.6 0 top
NOREF#135  -  []  13.05 49.05 0 top
NOREF#136  -  []  48.83 3.61 90 top
NOREF#137  -  []  16.51 25.93 90 top
NOREF#138  -  []  44.66 57.84 0 top
NOREF#139  -  []  38.81 53.23 0 top
NOREF#140  -  []  34.2 21.48 90 top
NOREF#141  -  []  47.01 56.99 90 top
NOREF#142  -  []  7.86 65.13 0 top
NOREF#143  -  []  31.83 61.28 90 top
NOREF#144  -  []  12.47 20.6 90 top
NOREF#145  -  []  44.82 42.77 90 top
NOREF#146  -  []  44.73 30.54 90 top
NOREF#147  -  []  10.95 0.32 0 top
NOREF#148  -  []  3.13 62.07 0 top
NOREF#149  -  []  36.45 17.54 90 top
NOREF#150  -  []  33.12 50.91 90 top
NOREF#151  -  []  24.87 14.93 0 top
NOREF#152  -  []  21.97 39.16 90 top
NOREF#153  -  []  11.2 13.53 0 top
NOREF#154  -  []  46.18 11.75 0 top
NOREF#155  -  []  26.8 32.29 0 top
NOREF#156  -  []  35.85 57.45 0 top
NOREF#157  -  []  22.22 13.59 0 top
NOREF#158  -  []  43.71 43.38 90 top
NOREF#159  -  []  10.62 14.09 0 top
NOREF#160  -  []  38.27 23.83 0 top
NOREF#161  -  []  30.24 34.16 90 top
NOREF#162  -  []  45.12 22.67 0 top
NOREF#163  -  []  15.32 7.12 0 top
NOREF#164  -  []  35.06 51.14 0 top
NOREF#165  -  []  27.63 60.98 0 top
NOREF#166  -  []  46.36 31.4 90 top
NOREF#167  -  []  32.39 14.81 90 top
NOREF#168  -  []  12.4 53.22 0 top
NOREF#169  -  []  33.95 24.8 0 top
NOREF#170  -  []  32.99 13.79 0 top
NOREF#171  -  []  43.11 4.06 90 top
NOREF#172  -  []  22.36 5.02 0 top
NOREF#173  -  []  20.41 6.27 90 top
NOREF#174  -  []  26.36 33.57 0 top
NOREF#175  -  []  11.56 64.08 90 top
NOREF#176  -  []  29.24 34.69 90 top
NOREF#177  -  []  13.46 53.21 90 top
NOREF#178  -  []  9.63 28.73 90 top
NOREF#179  -  []  39.95 35.7 0 top
NOREF#180  -  []  25.31 36.67 90 top
NOREF#181  -  []  34.44 31.3 0 top
NOREF#182  -  []  28.43 19.28 90 top
NOREF#183  -  []  43.93 45.74 0 top
NOREF#184  -  []  22.72 18.3 90 top
NOREF#185  -  []  38.31 39.22 90 top
NOREF#186  -  []  15.45 47.89 90 top
NOREF#187  -  []  35.4 11.89 90 top
NOREF#188  -  []  31 31.27 90 top
NOREF#189  -  []  10.44 20.37 0 top
NOREF#190  -  []  40.85 32 90 top
NOREF#191  -  []  44.1 62.25 0 top
NOREF#192  -  []  6.51 48.88 90 top
NOREF#193  -  []  40.55 39.8 90 top
NOREF#194  -  []  21.97 39.72 90 top
NOREF#195  -  []  22.22 13.88 0 top
NOREF#196  -  []  20.1 4.73 90 top
NOREF#197  -  []  29.14 37.63 0 top
NOREF#198  -  []  18.21 13.49 0 top
NOREF#199  -  []  43.21 22.16 90 top
NOREF#200  -  []  42.26 21.1 90 top
NOREF#201  -  []  38.72 52.52 90 top
NOREF#202  -  []  37.92 55.68 0 top
NOREF#203  -  []  19.12 31.76 90 top
NOREF#204  -  []  34.63 23.73 90 top
NOREF#205  -  []  28.03 63.7 0 top
NOREF#206  -  []  8.97 23.23 0 top
NOREF#207  -  []  13.11 6.73 90 top
NOREF#208  -  []  47.17 12.58 90 top
NOREF#209  -  []  44.1 61.16 0 top
NOREF#210  -  []  27.48 15.29 90 top
NOREF#211  -  []  37.05 17.54 0 top
NOREF#212  -  []  30.04 34.38 90 top
NOREF#213  -  []  31.45 65.61 0 top
NOREF#214  -  []  32 58.3 0 top
NOREF#215  -  []  34.57 53.94 0 top
NOREF#216  -  []  27.12 34.1 90 top
NOREF#217  -  []  16.65 38.62 0 top
NOREF#218  -  []  46.12 22.67 90 top
NOREF#219  -  []  41.81 10.01 90 top
NOREF#220  -  []  44.36 62.79 90 top
NOREF#221  -  []  46.19 16.61 90 top
NOREF#222  -  []  26.82 30.67 90 top
NOREF#223  -  []  36.94 57.45 90 top
NOREF#224  -  []  41.26 21.1 0 top
NOREF#225  -  []  39.11 54.31 90 top
NOREF#226  -  []  26.23 37.21 90 top
NOREF#227  -  []  34.73 50.59 90 top
NOREF#228  -  []  15.97 19.8 90 top
NOREF#229  -  []  27.76 33.89 90 top
NOREF#230  -  []  43.61 62.69 90 top
NOREF#231  -  []  43.12 4.84 90 top
NOREF#232  -  []  38.81 51.99 0 top
NOREF#233  -  []  30.26 61.27 90 top
NOREF#234  -  []  41.66 4.06 0 top
NOREF#235  -  []  40.15 32.88 90 top
NOREF#236  -  []  42.95 32.67 90 top
NOREF#237  -  []  31.07 33.01 0 top
NOREF#238  -  []  30.74 34.89 90 top
NOREF#239  -  [unnamed#2]  35.56 2.54 0 top
NOREF#240  -  []  28.91 63.41 90 top
NOREF#241  -  []  36.78 12.13 0 top
NOREF#242  -  []  38.29 18.86 0 top
NOREF#243  -  []  26.96 34.96 0 top
NOREF#244  -  []  28.54 31.51 90 top
NOREF#245  -  []  29.37 37.18 90 top
NOREF#246  -  []  30.08 36.26 90 top
NOREF#247  -  []  32.42 33.61 90 top
NOREF#248  -  []  18.01 50.09 90 top
NOREF#249  -  []  29.93 37.19 90 top
NOREF#250  -  []  37.07 36.55 0 top
NOREF#251  -  []  37.92 56.28 90 top
NOREF#252  -  []  19.65 49.79 90 top
NOREF#253  -  []  25 16.2 0 top
NOREF#254  -  []  19.05 34.95 0 top
NOREF#255  -  []  29.51 35.75 0 top
NOREF#256  -  []  38.27 24.83 90 top
NOREF#257  -  []  24.69 13.55 90 top
NOREF#258  -  []  8.31 29.54 0 top
NOREF#259  -  []  36.07 49.73 0 top
NOREF#260  -  []  31.59 33.02 0 top
NOREF#261  -  []  41.81 20.67 90 top
NOREF#262  -  []  27.4 36.95 0 top
NOREF#263  -  []  45.77 18.62 0 top
NOREF#264  -  []  39.01 42.75 90 top
NOREF#265  -  []  46.17 13.41 0 top
NOREF#266  -  []  37.81 10.46 90 top
NOREF#267  -  []  10.95 0.32 0 top
NOREF#268  -  []  13.34 20.21 0 top
NOREF#269  -  []  44.55 47.86 0 top
NOREF#270  -  []  39.63 42.92 90 top
NOREF#271  -  []  10.34 35.24 0 top
NOREF#272  -  []  12.85 5.1 0 top
NOREF#273  -  []  31.75 49.31 90 top
NOREF#274  -  []  8.44 13.65 90 top
NOREF#275  -  []  46.34 43.41 90 top
NOREF#276  -  []  29.68 38.23 90 top
NOREF#277  -  []  39.93 6.34 0 top
NOREF#278  -  []  16.29 31.24 90 top
NOREF#279  -  []  30.19 12.2 90 top
NOREF#280  -  []  34.45 63.21 0 top
NOREF#281  -  []  45.89 17.21 0 top
NOREF#282  -  []  33.66 32.96 90 top
NOREF#283  -  []  8.05 13.38 0 top
NOREF#284  -  []  35.14 15.42 0 top
NOREF#285  -  []  29.76 64.3 90 top
NOREF#286  -  []  31.39 21.63 90 top
NOREF#287  -  []  29.29 12.65 0 top
NOREF#288  -  []  35.41 8.97 0 top
NOREF#289  -  []  39.25 43.46 0 top
NOREF#290  -  []  32.66 54.63 90 top
NOREF#291  -  []  17.55 5.97 0 top
NOREF#292  -  []  40.49 11.8 90 top
NOREF#293  -  []  29.26 26.72 0 top
NOREF#294  -  []  10.03 64.55 90 top
NOREF#295  -  []  37.29 42.87 90 top
NOREF#296  -  []  39.87 43.14 90 top
NOREF#297  -  []  32.76 57.05 90 top
NOREF#298  -  []  25.69 31.64 90 top
NOREF#299  -  []  45.32 16.6 90 top
NOREF#300  -  []  37.16 32.7 90 top
NOREF#301  -  []  43.29 23.63 90 top
NOREF#302  -  []  32.2 67.21 90 top
NOREF#303  -  []  6.37 26.88 0 top
NOREF#304  -  []  24.72 75.11 90 top
NOREF#305  -  []  16.4 38.82 90 top
NOREF#306  -  []  35.88 56.24 90 top
NOREF#307  -  []  43.3 61.66 90 top
NOREF#308  -  []  25.74 33.17 90 top
NOREF#309  -  []  37.41 58.06 0 top
NOREF#310  -  []  42.96 41.65 90 top
NOREF#311  -  []  27.86 30.71 0 top
NOREF#312  -  []  34.42 61.21 0 top
NOREF#313  -  []  7.05 6.63 90 top
NOREF#314  -  []  14.22 19.61 90 top
NOREF#315  -  []  30.45 61.24 90 top
NOREF#316  -  []  30.99 36.59 0 top
NOREF#317  -  []  9.91 20.37 0 top
NOREF#318  -  []  28.46 30.71 90 top
NOREF#319  -  []  28.72 13.37 0 top
NOREF#320  -  []  12.98 6.28 90 top
NOREF#321  -  []  35.6 6.94 0 top
NOREF#322  -  []  20.28 4.69 90 top
NOREF#323  -  []  35.1 34.51 90 top
NOREF#324  -  []  31.32 14.66 90 top
NOREF#325  -  []  27.81 32.83 0 top
NOREF#326  -  []  17.08 46.45 0 top
NOREF#327  -  []  31.7 58.21 90 top
NOREF#328  -  []  36.7 53.46 0 top
NOREF#329  -  []  25.91 36.67 0 top
NOREF#330  -  []  42.57 20.14 0 top
NOREF#331  -  []  37.59 49.13 90 top
NOREF#332  -  []  34.74 55.64 0 top
NOREF#333  -  []  42.31 57.64 90 top
NOREF#334  -  []  17.93 24.62 90 top
NOREF#335  -  []  46.07 18.62 90 top
NOREF#336  -  []  21.98 4.75 0 top
NOREF#337  -  []  36.63 30.91 90 top
NOREF#338  -  []  8.23 13.35 90 top
NOREF#339  -  []  26.86 31.21 90 top
NOREF#340  -  []  40 59.64 90 top
NOREF#341  -  []  31.6 31.27 0 top
NOREF#342  -  []  14.26 14.13 0 top
NOREF#343  -  []  30.64 34.38 0 top
NOREF#344  -  []  45.02 3.61 90 top
NOREF#345  -  []  34.42 61.21 0 top
NOREF#346  -  []  13.86 49.13 90 top
NOREF#347  -  []  27.69 38.06 0 top
NOREF#348  -  []  31.73 16.1 0 top
NOREF#349  -  []  33.58 21.03 0 top
NOREF#350  -  []  30.49 7.45 0 top
NOREF#351  -  []  26.11 13.85 0 top
NOREF#352  -  []  27.15 38.35 0 top
NOREF#353  -  []  7.26 28.45 90 top
NOREF#354  -  []  38.95 31.9 0 top
NOREF#355  -  []  14.71 7.13 0 top
NOREF#356  -  []  31.59 61.55 0 top
NOREF#357  -  []  43.93 42.77 90 top
NOREF#358  -  []  35 30.01 90 top
NOREF#359  -  []  8.4 28.11 0 top
NOREF#360  -  []  44.51 47.86 0 top
NOREF#361  -  []  13.64 19.61 90 top
NOREF#362  -  []  7.05 6.52 90 top
NOREF#363  -  []  51.05 66.29 90 top
NOREF#364  -  []  43.44 18.79 90 top
NOREF#365  -  []  28.5 60.17 0 top
NOREF#366  -  []  13.17 6.25 90 top
NOREF#367  -  []  15.3 20.4 0 top
NOREF#368  -  []  17.3 20.71 90 top
NOREF#369  -  []  7.95 19.21 90 top
NOREF#370  -  []  36.56 32.7 0 top
NOREF#371  -  []  21.42 4.07 90 top
NOREF#372  -  []  14.11 45.02 0 top
NOREF#373  -  []  31.92 15.17 0 top
NOREF#374  -  []  41.81 10.46 90 top
NOREF#375  -  []  19.52 6.27 90 top
NOREF#376  -  []  42.17 59.02 0 top
NOREF#377  -  []  29.34 13.37 90 top
NOREF#378  -  []  36.86 27.03 0 top
NOREF#379  -  []  34.16 13.43 90 top
NOREF#380  -  []  34.44 30.7 90 top
NOREF#381  -  []  36.78 11.04 0 top
NOREF#382  -  []  22.22 13.56 90 top
NOREF#383  -  []  7.87 21.97 0 top
NOREF#384  -  []  33.92 35.31 90 top
NOREF#385  -  []  23.62 57.58 90 top
NOREF#386  -  []  10 43.14 0 top
NOREF#387  -  []  36.19 53.46 0 top
NOREF#388  -  []  18.26 6.19 0 top
NOREF#389  -  []  30.29 29.75 90 top
NOREF#390  -  []  33.67 9.99 90 top
NOREF#391  -  []  12.98 6.6 0 top
NOREF#392  -  []  36.25 11.04 0 top
NOREF#393  -  []  24.51 13.58 90 top
NOREF#394  -  []  46.23 46.71 0 top
NOREF#395  -  []  12.59 53.19 90 top
NOREF#396  -  []  25.98 14.33 90 top
NOREF#397  -  []  43.1 13.21 0 top
NOREF#398  -  []  25.25 59.63 0 top
NOREF#399  -  []  31.5 65.61 0 top
NOREF#400  -  []  15.54 14.13 0 top
NOREF#401  -  []  22.16 4.72 90 top
NOREF#402  -  []  14.58 13.51 90 top
NOREF#403  -  []  31.21 61.28 0 top
NOREF#404  -  []  29.56 26.12 90 top
NOREF#405  -  []  39.23 38.62 0 top
NOREF#406  -  []  39.45 4.93 0 top
NOREF#407  -  []  27.46 31.75 0 top
NOREF#408  -  []  1.61 44.98 90 top
NOREF#409  -  []  43.4 47.66 90 top
NOREF#410  -  []  10.23 28.73 0 top
NOREF#411  -  []  29.7 55.33 0 top
NOREF#412  -  []  8.9 21.61 90 top
NOREF#413  -  []  28.83 32.6 90 top
NOREF#414  -  []  43.44 19.81 90 top
NOREF#415  -  []  32.39 15.31 90 top
NOREF#416  -  []  25.14 33.17 0 top
NOREF#417  -  []  23.34 59.49 90 top
NOREF#418  -  []  31.59 61.55 90 top
NOREF#419  -  []  29.05 60.17 0 top
NOREF#420  -  []  45.12 20.64 0 top
